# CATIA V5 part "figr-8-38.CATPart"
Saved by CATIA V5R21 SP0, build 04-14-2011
Part number: Part2
Bounding box of the stored display mesh (mm): x -50 to 50, y -50 to 50, z 0 to 40
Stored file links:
  D:\CATIA V5R21 E-RESOURCES\CATIA-V5R21\catia-v5r21-prt\c08-catia-v5r20-prt\c08-catia-v5r21-figr-8-38.CATPart
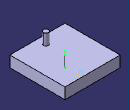
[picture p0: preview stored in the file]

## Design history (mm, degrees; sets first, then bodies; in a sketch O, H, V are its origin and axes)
Body1 (main body)
  Sketch1 on xy-plane, origin (0, 0, 0), H (1, 0, 0), V (0, 1, 0)
    line L1 (-50, 50) -> (50, 50)
    line L2 (50, 50) -> (50, -50)
    line L3 (50, -50) -> (-50, -50)
    line L4 (-50, -50) -> (-50, 50)
    axis line L5 (50, -50) -> (-50, 50)
    length L2 = 100
    length L3 = 100
    horizontal: L1 H, L3 H
    vertical: L2 V, L4 V
    midpoint: O L5
  Pad1: profile Sketch1, direction (0, 0, 1), length 20
  Sketch2 on face of Pad1, origin (0, 0, 20), H (1, 0, 0), V (0, 1, 0)
    circle A1 centre (0, -34.6458) radius 4.7511
    point P1 (0, -34.6458)
    coincidence: P1 V
  Pad2: profile Sketch2, direction (0, 0, 1), length 20
  Sketch3 on yz-plane, origin (0, 0, 0), H (0, 1, 0), V (0, 0, 1)
    line L1 (0, 0) -> (0, 20.0386)
    vertical: L1 V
